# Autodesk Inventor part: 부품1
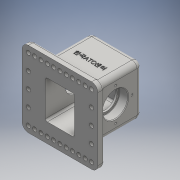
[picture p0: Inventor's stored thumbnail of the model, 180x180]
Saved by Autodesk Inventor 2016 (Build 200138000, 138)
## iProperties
Created: 2018-11
Part Number: 부품1
Material: 일반
Document SubType Name: Modeling
Designer: Administrator
Density: 1 g/cm^3
Appearance: 기본값
Mass: 376.663 g
Surface Area: 777.082 cm^2
Volume: 376.663 cm^3
Author: Administrator
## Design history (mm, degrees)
sketch "스케치2"
  geometry: L1 (40, 40)-(-40, 40); L2 (-40, 40)-(-40, -40); L3 (-40, -40)-(40, -40); L4 (40, -40)-(40, 40); L5 (40, 40)-(-40, -40); L6 (-40, 40)-(40, -40); 1 further point
  constraints: 12 end point, 2 midpoint, 2 parallel, 1 horizontal, 1 perpendicular
  dimensions: "d0" = 80 distance of L3.end L2.end; "d1" = 80 distance of L2.end L1.end
extrude "돌출1" new body sketch "스케치2" distance "d2" = 80; taper "d3" = 0 deg
sketch "스케치3"
  geometry: L1 (-60, -60)-(60, -60); L2 (60, -60)-(60, 60); L3 (60, 60)-(-60, 60); L4 (-60, 60)-(-60, -60); L5 (-60, -60)-(60, 60); L6 (60, -60)-(-60, 60); 1 further point
  constraints: 12 end point, 2 midpoint, 2 parallel, 1 horizontal, 1 perpendicular
  dimensions: "d4" = 120 distance between parallel lines of L2 L4; "d5" = 120 distance between parallel lines of L1 L3
extrude "돌출2" join sketch "스케치3" distance "d6" = 10; taper "d7" = 0 deg
sketch "스케치5"
  geometry: L1 (-23, -30)-(23, -30); L2 (23, -30)-(23, 30); L3 (23, 30)-(-23, 30); L4 (-23, 30)-(-23, -30); L5 (-23, -30)-(23, 30); L6 (23, -30)-(-23, 30); 1 further point
  constraints: 12 end point, 2 midpoint, 2 parallel, 1 horizontal, 1 perpendicular
  dimensions: "d8" = 46 distance of L3.end L2.end; "d10" = 60 distance between parallel lines of L1 L3
extrude "돌출3" cut sketch "스케치5" distance "d11" = 80; taper "d12" = 0 deg
sketch "스케치6"
  geometry: L1 (100, -90)-(-20, -90) reference; C1 r 20 at (40, -42); 1 further point
  constraints: 1 centre point
  dimensions: "d13" = 40 diameter of C1; "d14" = 48 distance from line of L1 C1.centre
extrude "돌출4" cut sketch "스케치6" distance "d15" = 14; taper "d16" = 0 deg
sketch "스케치7"
  geometry: C1 r 16.5 at (0, 0); 1 further point
  constraints: 1 centre point
  dimensions: "d17" = 33 diameter of C1
extrude "돌출5" cut sketch "스케치7" distance "d18" = 3; taper "d19" = 0 deg
sketch "스케치8"
  geometry: L1 (100, -90)-(-20, -90) reference; C1 r 20 at (40, -42); 1 further point
  constraints: 1 centre point
  dimensions: "d20" = 40 diameter of C1; "d21" = 48 distance from line of L1 C1.centre
extrude "돌출6" cut sketch "스케치8" distance "d22" = 14; taper "d23" = 0 deg
sketch "스케치9"
  geometry: C1 r 16.5 at (0, 0); 1 further point
  constraints: 1 centre point
  dimensions: "d24" = 33 diameter of C1
extrude "돌출7" cut sketch "스케치9" distance "d25" = 3; taper "d26" = 0 deg
sketch "스케치10"
  geometry: C1 r 7.5 at (0, 0); 1 further point
  constraints: 1 centre point, 1 coincident
  dimensions: "d27" = 15 diameter of C1
extrude "돌출8" join sketch "스케치10" distance "d28" = 5; taper "d29" = 0 deg
hole "구멍1" diameter "d32" = 4.917; stored, may be unused: countersink angle "d36" = 90 deg, drill point angle "d38" = 0 deg; dims "d30" = 10, "d31" = 10, "d33" = 12, "d34" = 4, "d35" = 2, "d37" = 60.85
fillet "모깎기1" dims "d39" = 8
sketch "스케치12"
  geometry: 29 further points
  dimensions: "d40" = 50 distance of point (0, 50) point (0, 0); "d41" = 50 distance of point (0, -50) point (0, 0); "d42" = 50 distance of point (-50, 0) point (0, 0); "d43" = 50 distance of point (50, 0) point (0, 0); "d44" = 10 distance of point (0, 50) point (10, 50); "d45" = 10 distance of point (20, 50) point (10, 50); "d46" = 10 distance of point (30, 50) point (20, 50); "d47" = 10 distance of point (40, 50) point (30, 50); "d48" = 10 distance of point (50, 50) point (40, 50); "d49" = 10 distance of point (-10, 50) point (0, 50); "d50" = 10 distance of point (-20, 50) point (-10, 50); "d51" = 10 distance of point (-40, 50) point (-30, 50); "d52" = 10 distance of point (-30, 50) point (-20, 50); "d53" = 10 distance of point (-50, 50) point (-40, 50); "d54" = 25 distance of point (-50, 25) point (-50, 50); "d55" = 25 distance of point (-50, 0) point (-50, 25); "d56" = 25 distance of point (-50, -25) point (-50, 0); "d57" = 25 distance of point (-50, -50) point (-50, -25); "d58" = 10 distance of point (-40, -50) point (-50, -50); "d59" = 10 distance of point (-30, -50) point (-40, -50); "d60" = 10 distance of point (-20, -50) point (-30, -50); "d61" = 10 distance of point (-10, -50) point (-20, -50); "d62" = 10 distance of point (0, -50) point (-10, -50); "d63" = 10 distance of point (0, -50) point (10, -50); "d64" = 10 distance of point (20, -50) point (10, -50); "d65" = 10 distance of point (20, -50) point (30, -50); "d66" = 10 distance of point (30, -50) point (40, -50); "d67" = 10 distance of point (40, -50) point (50, -50); "d68" = 25 distance of point (50, 25) point (50, 50); "d69" = 25 distance of point (50, 0) point (50, -25)
hole "구멍2" sketch "스케치12" diameter "d70" = 6.6; stored, may be unused: countersink angle "d74" = 90 deg, drill point angle "d76" = 0 deg; dims "d71" = 12, "d72" = 4, "d73" = 2, "d75" = 60.85
fillet "모깎기2" dims "d77" = 10
fillet "모깎기3" dims "d78" = 3
fillet "모깎기4" dims "d79" = 3
fillet "모깎기5" dims "d80" = 3
chamfer "모따기1" distance "d81" = 1; stored, may be unused: second distance "d82" = 2, angle "d83" = 45 deg
sketch "스케치13"
  geometry: L1 (82, -82)-(-18, -82) reference; A1 r 26 centre (32, -34) between (32, -8) and (6, -34); 3 further points
  constraints: 4 point on circle, 1 centre point
  dimensions: "d84" = 52 diameter of A1; "d85" = 48 distance from line of L1 A1.centre
hole "구멍3" sketch "스케치13" at (32, -8), (6, -34), (32, -60), (58, -34) diameter "d86" = 3.242; stored, may be unused: countersink angle "d90" = 90 deg, drill point angle "d92" = 118 deg; dims "d87" = 8, "d88" = 4, "d89" = 2, "d91" = 10
fillet "모깎기6" dims "d93" = 0.6
sketch "스케치16"
  geometry: L1 (82, -82)-(-18, -82) reference; 3 further points
  constraints: 1 midpoint, 1 vertical alignment, 1 other
  dimensions: "d94" = 48 distance from line of L1 point (32, -34)
feature "엠보싱1" sketch "스케치16" dims "d0" = 80, "d1" = 80, "d8" = 46, "d10" = 60, "d95" = 0.5, "d96" = 0
node "솔리드1"
mirror "대칭1"
